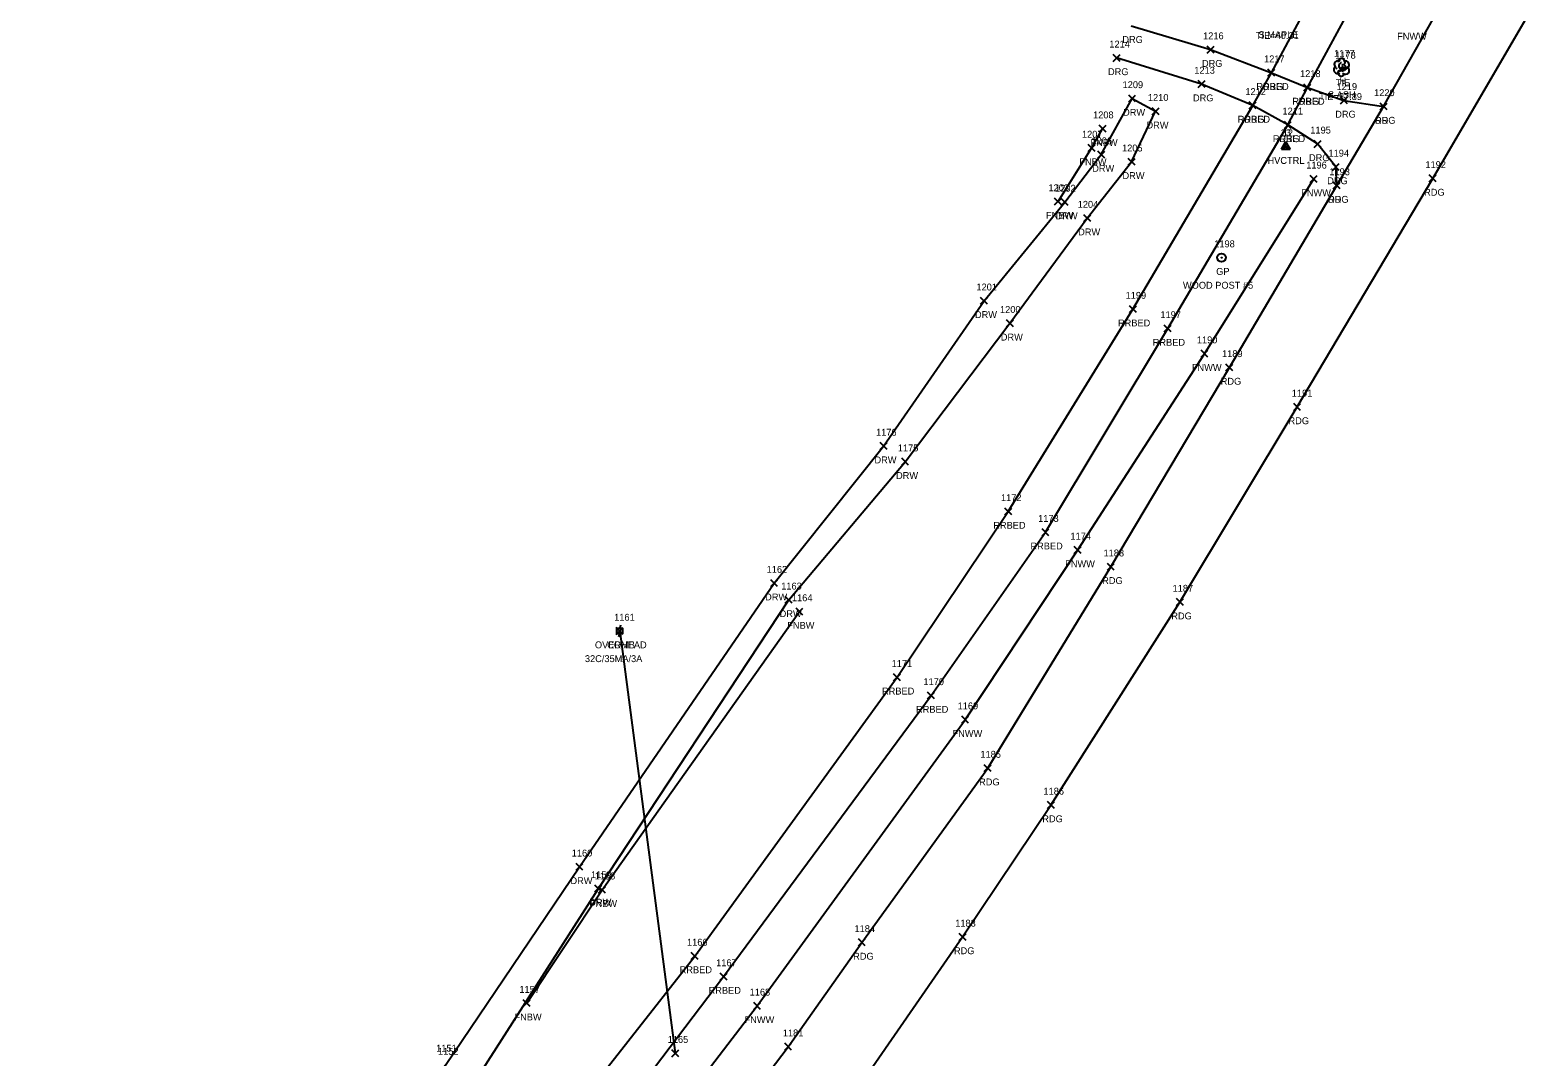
# Model space of a CAD drawing. Extents: x 1508122 to 1515053, y 865012 to 875267.
# Drawn here: x 1509138.2 to 1509575.3, y 866267.8 to 866565.4 of the extents above; entities that cross this region are included whole.
import ezdxf

# ---------------------------------------------------------------- set-up
doc = ezdxf.new("R2010")
doc.units = 0
for name, color, linetype in [('C_A', 7, 'Continuous'), ('C_C', 7, 'Continuous'), ('C_I', 7, 'Continuous'), ('CBP', 7, 'Continuous'), ('CPSM', 7, 'Continuous'), ('L_A', 7, 'Continuous'), ('L_C', 7, 'Continuous'), ('L_I', 7, 'Continuous'), ('L_TIC', 7, 'Continuous'), ('LFNC', 7, 'Continuous'), ('LTD', 7, 'Continuous'), ('P_A', 7, 'Continuous'), ('P_I', 7, 'Continuous'), ('P_TIC', 7, 'Continuous'), ('PEU', 7, 'Continuous'), ('R_A', 7, 'Continuous'), ('R_C', 7, 'Continuous'), ('R_I', 7, 'Continuous'), ('R_TIC', 7, 'Continuous'), ('RDG', 7, 'Continuous'), ('RDW', 7, 'Continuous'), ('RGP', 7, 'Continuous'), ('RRB', 7, 'Continuous'), ('U_A', 7, 'Continuous'), ('U_C', 7, 'Continuous'), ('U_I', 7, 'Continuous'), ('U_TIC', 7, 'Continuous'), ('UP', 7, 'Continuous'), ('UT', 7, 'Continuous')]:
    doc.layers.add(name, color=color, linetype=linetype)

msp = doc.modelspace()

# ---------------------------------------------------------------- linework, layer by layer
at = {"layer": 'CBP'}
for radius in [0.625, 0.0833]:
    msp.add_circle((1509518.66, 866554.11), radius, dxfattribs=at)
at = {"layer": 'CPSM'}
for p, q in [((1509500.96, 866530.87), (1509502.21, 866533.04)), ((1509500.99, 866530.89), (1509502.24, 866533.06)), ((1509503.46, 866530.87), (1509502.21, 866533.04)), ((1509502.21, 866531.59), (1509502.21, 866533.04)), ((1509503.49, 866530.89), (1509502.24, 866533.06)), ((1509502.24, 866531.62), (1509502.24, 866533.06)), ((1509500.96, 866530.87), (1509502.21, 866531.59)), ((1509500.96, 866530.87), (1509503.46, 866530.87)), ((1509500.99, 866530.89), (1509502.24, 866531.62)), ((1509500.99, 866530.89), (1509503.49, 866530.89)), ((1509502.21, 866531.59), (1509502.21, 866531.59)), ((1509502.21, 866531.59), (1509503.46, 866530.87)), ((1509502.24, 866531.62), (1509502.24, 866531.62)), ((1509502.24, 866531.62), (1509503.49, 866530.89))]:
    msp.add_line(p, q, dxfattribs=at)
at = {"layer": 'L_TIC'}
for points in [[(1509448.12, 866535.8), (1509450.12, 866537.8)], [(1509450.12, 866535.8), (1509448.12, 866537.8)], [(1509444.91, 866530.2), (1509446.91, 866532.2)], [(1509446.91, 866530.2), (1509444.91, 866532.2)], [(1509509.32, 866521.25), (1509511.32, 866523.25)], [(1509511.32, 866521.25), (1509509.32, 866523.25)], [(1509435.2, 866514.7), (1509437.2, 866516.7)], [(1509437.2, 866514.7), (1509435.2, 866516.7)], [(1509477.64, 866470.59), (1509479.64, 866472.59)], [(1509479.64, 866470.59), (1509477.64, 866472.59)], [(1509440.91, 866413.7), (1509442.91, 866415.7)], [(1509442.91, 866413.7), (1509440.91, 866415.7)], [(1509360.23, 866395.84), (1509362.23, 866397.84)], [(1509362.23, 866395.84), (1509360.23, 866397.84)], [(1509408.27, 866364.5), (1509410.27, 866366.5)], [(1509410.27, 866364.5), (1509408.27, 866366.5)], [(1509303.01, 866315.19), (1509305.01, 866317.19)], [(1509305.01, 866315.19), (1509303.01, 866317.19)], [(1509281.16, 866282.32), (1509283.16, 866284.32)], [(1509283.16, 866282.32), (1509281.16, 866284.32)], [(1509347.98, 866281.54), (1509349.98, 866283.54)], [(1509349.98, 866281.54), (1509347.98, 866283.54)]]:
    msp.add_lwpolyline(points, dxfattribs=at)
at = {"layer": 'LFNC'}
for points in [[(1509436.2, 866515.7), (1509445.91, 866531.2), (1509449.12, 866536.8)], [(1508724.58, 865616.04), (1508798.39, 865687.75), (1508875.38, 865763.51), (1508931.23, 865818.85), (1508982.18, 865869.29), (1509035.45, 865924.1), (1509094.95, 865982.16), (1509139.87, 866027.02), (1509167.95, 866059.98), (1509211.5, 866111.27), (1509258.33, 866167.82), (1509310.89, 866232.8), (1509348.98, 866282.54), (1509409.27, 866365.5), (1509441.91, 866414.7), (1509478.64, 866471.59), (1509510.32, 866522.25)], [(1509282.16, 866283.32), (1509304.01, 866316.19), (1509361.23, 866396.84)]]:
    msp.add_lwpolyline(points, dxfattribs=at)
at = {"layer": 'LTD'}
msp.add_line((1509518.35, 866554.64), (1509518.35, 866554.64), dxfattribs=at)
msp.add_line((1509518.35, 866554.64), (1509518.35, 866554.64), dxfattribs=at)
msp.add_arc((1509518.4, 866556.08), 1.05, 335.5272, 180.9563, dxfattribs=at)
for centre, major_axis, ratio, start_param, end_param in [((1509517.27, 866553.93), (0.58, -1.04), 0.959034, 3.141593, 6.283185), ((1509517.56, 866555.31), (1.21, -0.51), 0.895232, 1.570796, 4.712389), ((1509518.14, 866555.1), (-0.208, -0.792), 0.645439, 3.141593, 6.283185), ((1509518.85, 866554.48), (-0.5, 0.667), 0.989748, 3.141593, 6.283185), ((1509519.35, 866553.81), (-1.09, 0.79), 0.841452, 1.570796, 4.712389), ((1509519.39, 866555.23), (-1.14, -0.48), 0.949671, 1.570796, 4.712389), ((1509518.35, 866553.14), (0.26, 1.06), 0.942809, 1.570796, 4.712389), ((1509517.89, 866553.89), (-0.625, -0.083), 0.423636, 0, 3.141593)]:
    msp.add_ellipse(centre, major_axis=major_axis, ratio=ratio, start_param=start_param, end_param=end_param, dxfattribs=at)
at = {"layer": 'P_TIC'}
for points in [[(1509529.58, 866542.24), (1509531.58, 866544.24)], [(1509531.58, 866542.24), (1509529.58, 866544.24)], [(1509515.97, 866519.33), (1509517.97, 866521.33)], [(1509517.97, 866519.33), (1509515.97, 866521.33)], [(1509543.81, 866521.39), (1509545.81, 866523.39)], [(1509545.81, 866521.39), (1509543.81, 866523.39)], [(1509484.86, 866466.6), (1509486.86, 866468.6)], [(1509486.86, 866466.6), (1509484.86, 866468.6)], [(1509504.51, 866455.15), (1509506.51, 866457.15)], [(1509506.51, 866455.15), (1509504.51, 866457.15)], [(1509450.5, 866408.82), (1509452.5, 866410.82)], [(1509452.5, 866408.82), (1509450.5, 866410.82)], [(1509470.53, 866398.58), (1509472.53, 866400.58)], [(1509472.53, 866398.58), (1509470.53, 866400.58)], [(1509414.81, 866350.46), (1509416.81, 866352.46)], [(1509416.81, 866350.46), (1509414.81, 866352.46)], [(1509433.14, 866339.77), (1509435.14, 866341.77)], [(1509435.14, 866339.77), (1509433.14, 866341.77)], [(1509378.31, 866299.93), (1509380.31, 866301.93)], [(1509380.31, 866299.93), (1509378.31, 866301.93)], [(1509407.52, 866301.52), (1509409.52, 866303.52)], [(1509409.52, 866301.52), (1509407.52, 866303.52)], [(1509356.97, 866269.69), (1509358.97, 866271.69)], [(1509358.97, 866269.69), (1509356.97, 866271.69)]]:
    msp.add_lwpolyline(points, dxfattribs=at)
at = {"layer": 'PEU'}
for points in [[(1508834.79, 865646.55), (1508872.67, 865695.62), (1508920.37, 865755), (1508947.99, 865790.47), (1508992.59, 865844.04), (1509029.62, 865887.05), (1509074.71, 865938.15), (1509076.21, 865938.91), (1509118.9, 865986.57), (1509166.14, 866040.81), (1509208.36, 866088.99), (1509242.04, 866127.91), (1509279.45, 866172.09), (1509325.23, 866227.62), (1509357.97, 866270.69), (1509379.31, 866300.93), (1509415.81, 866351.46), (1509451.5, 866409.82), (1509485.86, 866467.6), (1509516.97, 866520.33), (1509530.58, 866543.24), (1509548.88, 866575.75)], [(1508854.52, 865631.8), (1508891.73, 865680.86), (1508929.69, 865727.93), (1508966.84, 865774.38), (1509011.87, 865829.05), (1509047.63, 865870.06), (1509091.96, 865920.06), (1509093.12, 865920.34), (1509137.51, 865972.18), (1509182.39, 866021.44), (1509229.98, 866075.59), (1509259.93, 866112.51), (1509305, 866163.55), (1509344.16, 866211.55), (1509376.26, 866255.88), (1509408.52, 866302.52), (1509434.14, 866340.77), (1509471.53, 866399.58), (1509505.51, 866456.15), (1509544.81, 866522.39), (1509575.28, 866574.69)]]:
    msp.add_lwpolyline(points, dxfattribs=at)
at = {"layer": 'R_TIC'}
for points in [[(1509479.42, 866558.73), (1509481.42, 866560.73)], [(1509481.42, 866558.73), (1509479.42, 866560.73)], [(1509452.18, 866556.33), (1509454.18, 866558.33)], [(1509454.18, 866556.33), (1509452.18, 866558.33)], [(1509476.81, 866548.74), (1509478.81, 866550.74)], [(1509478.81, 866548.74), (1509476.81, 866550.74)], [(1509497.04, 866552.04), (1509499.04, 866554.04)], [(1509499.04, 866552.04), (1509497.04, 866554.04)], [(1509497.04, 866552.04), (1509499.04, 866554.04)], [(1509499.04, 866552.04), (1509497.04, 866554.04)], [(1509456.68, 866544.56), (1509458.68, 866546.56)], [(1509458.68, 866544.56), (1509456.68, 866546.56)], [(1509507.47, 866547.76), (1509509.47, 866549.76)], [(1509509.47, 866547.76), (1509507.47, 866549.76)], [(1509507.47, 866547.76), (1509509.47, 866549.76)], [(1509509.47, 866547.76), (1509507.47, 866549.76)], [(1509518.05, 866544.01), (1509520.05, 866546.01)], [(1509520.05, 866544.01), (1509518.05, 866546.01)], [(1509463.46, 866540.85), (1509465.46, 866542.85)], [(1509465.46, 866540.85), (1509463.46, 866542.85)], [(1509463.46, 866540.85), (1509465.46, 866542.85)], [(1509465.46, 866540.85), (1509463.46, 866542.85)], [(1509491.63, 866542.56), (1509493.63, 866544.56)], [(1509493.63, 866542.56), (1509491.63, 866544.56)], [(1509491.63, 866542.56), (1509493.63, 866544.56)], [(1509493.63, 866542.56), (1509491.63, 866544.56)], [(1509529.58, 866542.24), (1509531.58, 866544.24)], [(1509531.58, 866542.24), (1509529.58, 866544.24)], [(1509501.81, 866536.91), (1509503.81, 866538.91)], [(1509503.81, 866536.91), (1509501.81, 866538.91)], [(1509501.81, 866536.91), (1509503.81, 866538.91)], [(1509503.81, 866536.91), (1509501.81, 866538.91)], [(1509510.44, 866531.4), (1509512.44, 866533.4)], [(1509512.44, 866531.4), (1509510.44, 866533.4)], [(1509447.72, 866528.31), (1509449.72, 866530.31)], [(1509449.72, 866528.31), (1509447.72, 866530.31)], [(1509456.51, 866526.21), (1509458.51, 866528.21)], [(1509458.51, 866526.21), (1509456.51, 866528.21)], [(1509515.72, 866524.72), (1509517.72, 866526.72)], [(1509517.72, 866524.72), (1509515.72, 866526.72)], [(1509515.97, 866519.33), (1509517.97, 866521.33)], [(1509517.97, 866519.33), (1509515.97, 866521.33)], [(1509437.11, 866514.54), (1509439.11, 866516.54)], [(1509439.11, 866514.54), (1509437.11, 866516.54)], [(1509443.66, 866509.88), (1509445.66, 866511.88)], [(1509445.66, 866509.88), (1509443.66, 866511.88)], [(1509413.73, 866485.92), (1509415.73, 866487.92)], [(1509415.73, 866485.92), (1509413.73, 866487.92)], [(1509456.91, 866483.5), (1509458.91, 866485.5)], [(1509458.91, 866483.5), (1509456.91, 866485.5)], [(1509421.23, 866479.4), (1509423.23, 866481.4)], [(1509423.23, 866479.4), (1509421.23, 866481.4)], [(1509466.99, 866477.89), (1509468.99, 866479.89)], [(1509468.99, 866477.89), (1509466.99, 866479.89)], [(1509384.61, 866443.81), (1509386.61, 866445.81)], [(1509386.61, 866443.81), (1509384.61, 866445.81)], [(1509390.86, 866439.27), (1509392.86, 866441.27)], [(1509392.86, 866439.27), (1509390.86, 866441.27)], [(1509420.76, 866424.85), (1509422.76, 866426.85)], [(1509422.76, 866424.85), (1509420.76, 866426.85)], [(1509431.54, 866418.84), (1509433.54, 866420.84)], [(1509433.54, 866418.84), (1509431.54, 866420.84)], [(1509352.91, 866404.07), (1509354.91, 866406.07)], [(1509354.91, 866404.07), (1509352.91, 866406.07)], [(1509357.12, 866399.23), (1509359.12, 866401.23)], [(1509359.12, 866399.23), (1509357.12, 866401.23)], [(1509388.52, 866376.79), (1509390.52, 866378.79)], [(1509390.52, 866376.79), (1509388.52, 866378.79)], [(1509398.39, 866371.51), (1509400.39, 866373.51)], [(1509400.39, 866371.51), (1509398.39, 866373.51)], [(1509296.47, 866321.84), (1509298.47, 866323.84)], [(1509298.47, 866321.84), (1509296.47, 866323.84)], [(1509301.94, 866315.58), (1509303.94, 866317.58)], [(1509303.94, 866315.58), (1509301.94, 866317.58)], [(1509329.87, 866296), (1509331.87, 866298)], [(1509331.87, 866296), (1509329.87, 866298)], [(1509338.25, 866290.04), (1509340.25, 866292.04)], [(1509340.25, 866290.04), (1509338.25, 866292.04)]]:
    msp.add_lwpolyline(points, dxfattribs=at)
at = {"layer": 'RDG'}
for points in [[(1509457.34, 866566.66), (1509480.42, 866559.73), (1509498.04, 866553.04), (1509508.47, 866548.76), (1509519.05, 866545.01), (1509530.58, 866543.24)], [(1509516.97, 866520.33), (1509516.72, 866525.72), (1509511.44, 866532.4), (1509502.81, 866537.91), (1509492.63, 866543.56), (1509477.81, 866549.74), (1509453.18, 866557.33)]]:
    msp.add_lwpolyline(points, dxfattribs=at)
at = {"layer": 'RDW'}
for points in [[(1509175.42, 866106.26), (1509173.32, 866120.57), (1509180.1, 866134.99), (1509214.09, 866195.75), (1509258.58, 866265.37), (1509297.47, 866322.84), (1509353.91, 866405.07), (1509385.61, 866444.81), (1509414.73, 866486.92), (1509438.11, 866515.54), (1509448.72, 866529.31), (1509457.68, 866545.56), (1509464.46, 866541.85)], [(1509184.3, 866117.22), (1509182.8, 866124.3), (1509185.58, 866131.81), (1509224.08, 866190.75), (1509266.32, 866259.4), (1509302.94, 866316.58), (1509358.12, 866400.23), (1509391.86, 866440.27), (1509422.23, 866480.4), (1509444.66, 866510.88), (1509457.51, 866527.21), (1509464.46, 866541.85)]]:
    msp.add_lwpolyline(points, dxfattribs=at)
at = {"layer": 'RGP'}
msp.add_line((1509483.6, 866499.43), (1509483.6, 866499.43), dxfattribs=at)
for radius in [1.25, 0.0833]:
    msp.add_circle((1509483.6, 866499.43), radius, dxfattribs=at)
at = {"layer": 'RRB'}
for points in [[(1508639.82, 865572.96), (1508703.07, 865634.54), (1508776.82, 865704.61), (1508856.34, 865784.12), (1508912.2, 865838.55), (1508964.7, 865888.82), (1509016.49, 865939.79), (1509080.96, 866005.09), (1509118.28, 866044.61), (1509147.09, 866075.05), (1509175.42, 866106.26), (1509184.3, 866117.22), (1509238.52, 866181.83), (1509292.05, 866247.49), (1509330.87, 866297), (1509389.52, 866377.79), (1509421.76, 866425.85), (1509457.91, 866484.5), (1509492.63, 866543.56), (1509498.04, 866553.04), (1509526.06, 866605.21)], [(1508711.19, 865626.15), (1508783.92, 865697.13), (1508865.8, 865776.48), (1508920.93, 865830.03), (1508972.14, 865881.23), (1509024.12, 865931.95), (1509088.71, 865997.8), (1509126.76, 866037.79), (1509155.51, 866067.3), (1509199.41, 866116.81), (1509248.17, 866174.34), (1509301.29, 866241.12), (1509339.25, 866291.04), (1509399.39, 866372.51), (1509432.54, 866419.84), (1509467.99, 866478.89), (1509502.81, 866537.91), (1509508.47, 866548.76), (1509536.84, 866601.03)]]:
    msp.add_lwpolyline(points, dxfattribs=at)
at = {"layer": 'U_TIC'}
for points in [[(1509308.13, 866390.19), (1509310.13, 866392.19)], [(1509310.13, 866390.19), (1509308.13, 866392.19)], [(1509324.22, 866267.82), (1509326.22, 866269.82)], [(1509326.22, 866267.82), (1509324.22, 866269.82)]]:
    msp.add_lwpolyline(points, dxfattribs=at)
at = {"layer": 'UP'}
for p, q in [((1509309.38, 866392.86), (1509309.13, 866392.02)), ((1509308.3, 866390.36), (1509308.3, 866392.02)), ((1509308.3, 866392.02), (1509309.96, 866392.02)), ((1509309.96, 866390.36), (1509308.3, 866390.36)), ((1509308.88, 866389.52), (1509309.13, 866390.36)), ((1509309.13, 866391.19), (1509309.13, 866391.19)), ((1509309.96, 866392.02), (1509309.96, 866390.36))]:
    msp.add_line(p, q, dxfattribs=at)
msp.add_circle((1509309.13, 866391.19), 0.833, dxfattribs=at)
at = {"layer": 'UT'}
msp.add_lwpolyline([(1509309.13, 866391.19), (1509325.22, 866268.82)], dxfattribs=at)

# ---------------------------------------------------------------- texts
at = {"layer": 'C_A'}
for s, p in [('TIE', (1509516.74, 866549.11)), ('HVCTRL', (1509496.91, 866526.59)), ('HVCTRL', (1509496.93, 866526.62))]:
    msp.add_text(s, height=2, dxfattribs=at).set_placement(p)
at = {"layer": 'C_C'}
for s, p in [('TIE=40.31', (1509493.55, 866562.83)), ('TIE=27.89', (1509511.88, 866545.11))]:
    msp.add_text(s, height=2, dxfattribs=at).set_placement(p)
at = {"layer": 'C_I'}
for s, p in [('1178', (1509516.53, 866557.11)), ('23', (1509500.77, 866534.62)), ('12', (1509501.32, 866534.59))]:
    msp.add_text(s, height=2, dxfattribs=at).set_placement(p)
at = {"layer": 'L_A'}
for s, p in [('FNWW', (1509534.47, 866562.6)), ('H', (1509517.78, 866549.64)), ('FNBW', (1509445.59, 866531.8)), ('FNBW', (1509442.38, 866526.2)), ('FNWW', (1509506.67, 866517.25)), ('FNBW', (1509432.67, 866510.7)), ('FNWW', (1509474.99, 866466.59)), ('FNWW', (1509438.26, 866409.7)), ('FNBW', (1509357.7, 866391.84)), ('FNWW', (1509405.61, 866360.5)), ('FNBW', (1509300.48, 866311.19)), ('FNBW', (1509278.63, 866278.32)), ('FNWW', (1509345.32, 866277.54))]:
    msp.add_text(s, height=2, dxfattribs=at).set_placement(p)
at = {"layer": 'L_C'}
for s, p in [('S.MAPLE', (1509494.27, 866563.06)), ('S.ASH', (1509514.43, 866545.64))]:
    msp.add_text(s, height=2, dxfattribs=at).set_placement(p)
at = {"layer": 'L_I'}
for s, p in [('1177', (1509516.22, 866557.64)), ('1208', (1509446.35, 866539.8)), ('1207', (1509443.13, 866534.2)), ('1196', (1509508.14, 866525.25)), ('1203', (1509433.42, 866518.7)), ('1190', (1509476.43, 866474.59)), ('1174', (1509439.79, 866417.7)), ('1164', (1509359.05, 866399.84)), ('1169', (1509407.09, 866368.5)), ('1158', (1509301.89, 866319.19)), ('1157', (1509280.04, 866286.32)), ('1168', (1509346.8, 866285.54)), ('1151', (1509255.92, 866269.27))]:
    msp.add_text(s, height=2, dxfattribs=at).set_placement(p)
at = {"layer": 'P_A'}
for p in [(1509528.07, 866538.24), (1509542.3, 866517.39), (1509514.46, 866515.33), (1509483.35, 866462.6), (1509503, 866451.15), (1509448.99, 866404.82), (1509469.02, 866394.58), (1509413.3, 866346.46), (1509431.63, 866335.77), (1509376.8, 866295.93), (1509406.01, 866297.52)]:
    msp.add_text('RDG', height=2, dxfattribs=at).set_placement(p)
at = {"layer": 'P_I'}
for s, p in [('1220', (1509527.8, 866546.24)), ('1193', (1509514.84, 866523.33)), ('1192', (1509542.68, 866525.39)), ('1189', (1509483.73, 866470.6)), ('1191', (1509503.95, 866459.15)), ('1188', (1509449.38, 866412.82)), ('1187', (1509469.4, 866402.58)), ('1185', (1509413.68, 866354.46)), ('1186', (1509431.96, 866343.77)), ('1184', (1509377.19, 866303.93)), ('1183', (1509406.39, 866305.52)), ('1181', (1509356.41, 866273.69))]:
    msp.add_text(s, height=2, dxfattribs=at).set_placement(p)
at = {"layer": 'R_A'}
for s, p in [('DRG', (1509454.83, 866561.66)), ('DRG', (1509450.67, 866552.33)), ('DRG', (1509477.91, 866554.73)), ('RRBED', (1509493.69, 866548.04)), ('DRG', (1509495.53, 866548.04)), ('DRG', (1509475.3, 866544.74)), ('RRBED', (1509504.11, 866543.76)), ('DRG', (1509505.95, 866543.76)), ('DRW', (1509455.05, 866540.56)), ('DRG', (1509516.54, 866540.01)), ('DRW', (1509461.83, 866536.85)), ('DRW', (1509461.83, 866536.85)), ('RRBED', (1509488.28, 866538.56)), ('DRG', (1509490.12, 866538.56)), ('DRG', (1509528.07, 866538.24)), ('RRBED', (1509498.46, 866532.91)), ('DRG', (1509500.3, 866532.91)), ('DRG', (1509508.93, 866527.4)), ('DRW', (1509446.09, 866524.31)), ('DRW', (1509454.88, 866522.21)), ('DRG', (1509514.21, 866520.72)), ('DRG', (1509514.46, 866515.33)), ('DRW', (1509435.48, 866510.54)), ('DRW', (1509442.03, 866505.88)), ('GP', (1509482.03, 866494.43)), ('DRW', (1509412.1, 866481.92)), ('RRBED', (1509453.56, 866479.5)), ('DRW', (1509419.6, 866475.4)), ('RRBED', (1509463.64, 866473.89)), ('DRW', (1509382.98, 866439.81)), ('DRW', (1509389.23, 866435.27)), ('RRBED', (1509417.41, 866420.85)), ('RRBED', (1509428.19, 866414.84)), ('DRW', (1509351.28, 866400.07)), ('DRW', (1509355.49, 866395.23)), ('RRBED', (1509385.17, 866372.79)), ('RRBED', (1509395.03, 866367.51)), ('DRW', (1509294.85, 866317.84)), ('DRW', (1509300.31, 866311.58)), ('RRBED', (1509326.51, 866292)), ('RRBED', (1509334.89, 866286.04))]:
    msp.add_text(s, height=2, dxfattribs=at).set_placement(p)
at = {"layer": 'R_C'}
msp.add_text('WOOD POST #5', height=2, dxfattribs=at).set_placement((1509472.4, 866490.43))
at = {"layer": 'R_I'}
for s, p in [('1216', (1509478.24, 866562.73)), ('1214', (1509451.06, 866560.33)), ('1213', (1509475.69, 866552.74)), ('1217', (1509495.92, 866556.04)), ('1217', (1509495.92, 866556.04)), ('1209', (1509454.9, 866548.56)), ('1218', (1509506.34, 866551.76)), ('1218', (1509506.34, 866551.76)), ('1219', (1509516.92, 866548.01)), ('1210', (1509462.24, 866544.85)), ('1210', (1509462.24, 866544.85)), ('1212', (1509490.5, 866546.56)), ('1212', (1509490.5, 866546.56)), ('1220', (1509527.8, 866546.24)), ('1211', (1509501.25, 866540.91)), ('1211', (1509501.25, 866540.91)), ('1195', (1509509.32, 866535.4)), ('1206', (1509445.89, 866532.31)), ('1205', (1509454.74, 866530.21)), ('1194', (1509514.59, 866528.72)), ('1193', (1509514.84, 866523.33)), ('1202', (1509435.34, 866518.54)), ('1204', (1509441.89, 866513.88)), ('1198', (1509481.47, 866502.43)), ('1201', (1509412.53, 866489.92)), ('1199', (1509455.78, 866487.5)), ('1200', (1509419.37, 866483.4)), ('1197', (1509465.87, 866481.89)), ('1176', (1509383.43, 866447.81)), ('1175', (1509389.74, 866443.27)), ('1172', (1509419.64, 866428.85)), ('1173', (1509430.42, 866422.84)), ('1162', (1509351.73, 866408.07)), ('1163', (1509355.94, 866403.23)), ('1171', (1509387.96, 866380.79)), ('1170', (1509397.17, 866375.51)), ('1160', (1509295.22, 866325.84)), ('1159', (1509300.81, 866319.58)), ('1166', (1509328.64, 866300)), ('1167', (1509337.08, 866294.04)), ('1152', (1509256.46, 866268.37))]:
    msp.add_text(s, height=2, dxfattribs=at).set_placement(p)
at = {"layer": 'U_A'}
for s, p in [('OVERHEAD', (1509301.94, 866386.19)), ('COMB', (1509305.51, 866386.19))]:
    msp.add_text(s, height=2, dxfattribs=at).set_placement(p)
at = {"layer": 'U_C'}
msp.add_text('32C/35MA/3A', height=2, dxfattribs=at).set_placement((1509299.04, 866382.19))
at = {"layer": 'U_I'}
for s, p in [('1161', (1509307.52, 866394.19)), ('1161', (1509307.52, 866394.19)), ('1165', (1509323.04, 866271.82))]:
    msp.add_text(s, height=2, dxfattribs=at).set_placement(p)

doc.saveas('drawing.dxf')
